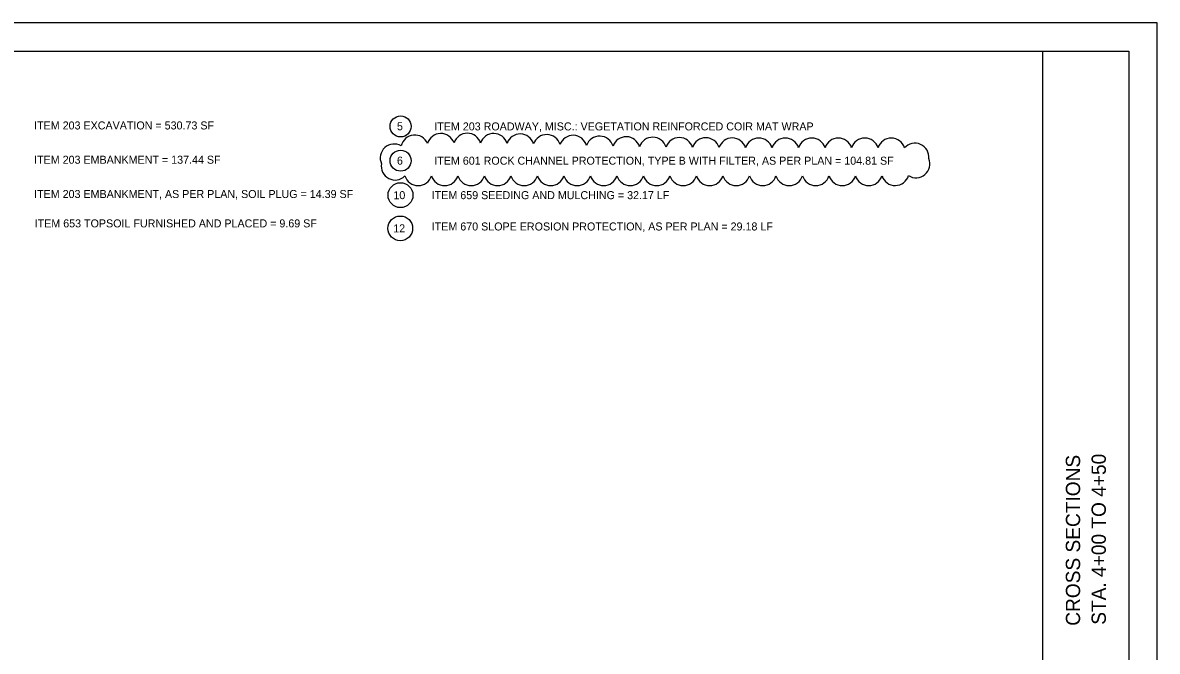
# Model space of a CAD drawing. Extents: x 0 to 34, y 0 to 22.
# Drawn here: x 14.15 to 34, y 11 to 22 of the extents above; entities that cross this region are included whole.
import ezdxf

# ---------------------------------------------------------------- set-up
doc = ezdxf.new("R2010")
doc.units = 0
for name, color, linetype in [('CS-ALGN-TEXT', 7, 'Continuous'), ('CS-ANNO', 7, 'Continuous'), ('CS-ANNO-MATC', 7, 'Continuous'), ('CS-ANNO-MATC-TEXT', 7, 'Continuous')]:
    doc.layers.add(name, color=color, linetype=linetype)

msp = doc.modelspace()

# ---------------------------------------------------------------- linework, layer by layer
at = {"layer": 'CS-ANNO'}
msp.add_lwpolyline([(0, 0), (34, 0), (34, 22), (0, 22)], close=True, dxfattribs=at)
at = {"layer": 'CS-ANNO-MATC'}
msp.add_line((32, 0.5), (32, 21.5), dxfattribs=at)
msp.add_lwpolyline([(1.5, 21.5), (33.5, 21.5), (33.5, 0.5), (1.5, 0.5)], close=True, dxfattribs=at)
at = {"layer": 'CS-ANNO-MATC-TEXT'}
for centre, radius in [((20.763, 20.185), 0.184), ((20.763, 19.585), 0.184), ((20.761, 18.982), 0.218), ((20.758, 18.401), 0.216)]:
    msp.add_circle(centre, radius, dxfattribs=at)
for centre, start, end in [((21.467, 19.818), 18.6842, 163.6842), ((21.929, 19.822), 17.3304, 162.3304), ((22.392, 19.818), 16.7299, 161.7299), ((22.855, 19.81), 16.3044, 161.3044), ((20.649, 19.634), 59.5605, 204.5605), ((21.01, 19.792), 22.8042, 167.8042), ((23.318, 19.799), 15.9783, 160.9783), ((23.781, 19.786), 15.7267, 160.7267), ((24.245, 19.772), 15.9239, 160.9239), ((24.709, 19.761), 16.297, 161.297), ((25.173, 19.753), 16.6107, 161.6107), ((25.637, 19.747), 16.8792, 161.8792), ((26.101, 19.743), 17.1124, 162.1124), ((26.565, 19.74), 17.3174, 162.3174), ((27.028, 19.739), 17.4782, 162.4782), ((27.492, 19.739), 17.5, 162.5), ((27.956, 19.739), 17.5, 162.5), ((28.419, 19.739), 17.5, 162.5), ((28.883, 19.739), 17.5, 162.5), ((29.346, 19.737), 17.006, 162.006), ((29.761, 19.648), 353.8328, 138.8328), ((20.667, 19.49), 169.9285, 314.9285), ((29.779, 19.529), 237.5469, 22.5469), ((21.07, 19.392), 197.5, 342.5), ((21.534, 19.392), 197.5, 342.5), ((21.998, 19.392), 197.5, 342.5), ((22.461, 19.392), 197.5, 342.5), ((22.925, 19.392), 197.5, 342.5), ((23.389, 19.392), 197.5, 342.5), ((23.852, 19.392), 197.5, 342.5), ((24.316, 19.392), 197.5, 342.5), ((24.78, 19.392), 197.5, 342.5), ((25.243, 19.392), 197.5, 342.5), ((25.707, 19.392), 197.5, 342.5), ((26.17, 19.392), 197.5, 342.5), ((26.634, 19.392), 197.5, 342.5), ((27.098, 19.392), 197.5, 342.5), ((27.561, 19.392), 197.5, 342.5), ((28.025, 19.392), 197.5, 342.5), ((28.489, 19.392), 197.5, 342.5), ((28.952, 19.392), 197.5, 342.5), ((29.415, 19.394), 198.2125, 343.2125)]:
    msp.add_arc(centre, 0.243, start, end, dxfattribs=at)

# ---------------------------------------------------------------- texts
at = {"layer": 'CS-ALGN-TEXT'}
for s, p in [('CROSS SECTIONS', (32.65, 11.447)), ('STA. 4+00 TO 4+50', (33.1, 11.465))]:
    msp.add_text(s, height=0.25, rotation=90, dxfattribs=at).set_placement(p)
at = {"layer": 'CS-ANNO-MATC-TEXT'}
for s, p in [('ITEM 203 EXCAVATION = 530.73 SF', (14.352, 20.132)), ('5', (20.7, 20.118)), ('ITEM 203 ROADWAY, MISC.: VEGETATION REINFORCED COIR MAT WRAP', (21.352, 20.115)), ('ITEM 203 EMBANKMENT = 137.44 SF', (14.352, 19.532)), ('6', (20.699, 19.516)), ('ITEM 601 ROCK CHANNEL PROTECTION, TYPE B WITH FILTER, AS PER PLAN = 104.81 SF', (21.352, 19.515)), ('ITEM 203 EMBANKMENT, AS PER PLAN, SOIL PLUG = 14.39 SF', (14.352, 18.932)), ('ITEM 659 SEEDING AND MULCHING = 32.17 LF', (21.308, 18.912)), ('ITEM 653 TOPSOIL FURNISHED AND PLACED = 9.69 SF', (14.362, 18.418)), ('ITEM 670 SLOPE EROSION PROTECTION, AS PER PLAN = 29.18 LF', (21.308, 18.364))]:
    msp.add_text(s, height=0.14, dxfattribs=at).set_placement(p)
for s, p in [('10', (20.638, 18.91)), ('12', (20.636, 18.329))]:
    msp.add_text(s, height=0.14, rotation=1, dxfattribs=at).set_placement(p)

doc.saveas('drawing.dxf')
